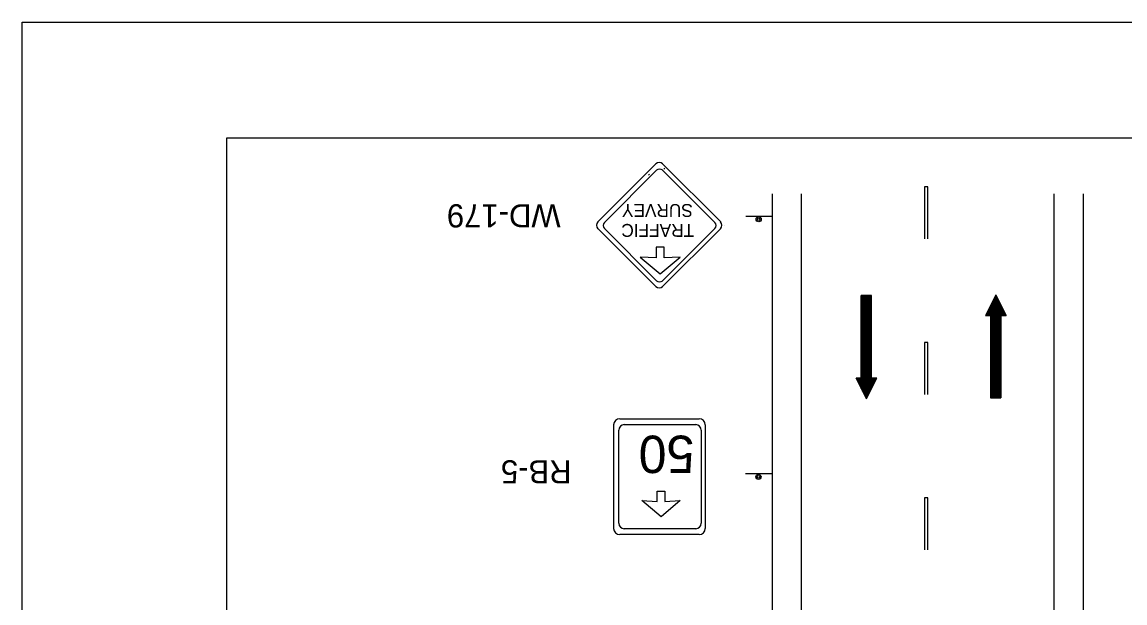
# Model space of a CAD drawing. Extents: x 1361 to 1577, y 123 to 402.
# Drawn here: x 1361.1 to 1464.1, y 347.9 to 402.1 of the extents above; entities that cross this region are included whole.
import ezdxf

# ---------------------------------------------------------------- set-up
doc = ezdxf.new("R2010")
doc.units = 0
for name, color, linetype in [('Level 10', 7, 'Continuous'), ('Level 2', 7, 'Continuous'), ('Level 44', 7, 'Continuous'), ('Level 60', 7, 'Continuous')]:
    doc.layers.add(name, color=color, linetype=linetype)

msp = doc.modelspace()

# ---------------------------------------------------------------- linework, layer by layer
at = {"layer": 'Level 10'}
for p, q in [((1431.16, 386.06), (1431.16, 139.68)), ((1433.87, 386.06), (1433.87, 139.68)), ((1457.45, 386.06), (1457.45, 139.68)), ((1460.18, 386.06), (1460.18, 139.68)), ((1439.47, 368.86), (1439.47, 376.56)), ((1440.43, 376.56), (1439.47, 376.56)), ((1439.47, 367.89), (1439.47, 376.56)), ((1439.59, 367.65), (1439.59, 376.56)), ((1439.71, 367.41), (1439.71, 376.56)), ((1439.83, 367.17), (1439.83, 376.56)), ((1439.95, 366.93), (1439.95, 376.56)), ((1440.07, 367.17), (1440.07, 376.56)), ((1440.19, 367.41), (1440.19, 376.56)), ((1440.31, 367.65), (1440.31, 376.56)), ((1440.43, 368.86), (1440.43, 376.56)), ((1440.43, 367.89), (1440.43, 376.56)), ((1452.02, 376.63), (1451.06, 374.71)), ((1451.66, 375.91), (1451.66, 367.01)), ((1451.78, 376.15), (1451.78, 367.01)), ((1451.9, 376.39), (1451.9, 367.01)), ((1452.02, 376.63), (1452.02, 367.01)), ((1452.02, 376.63), (1452.98, 374.71)), ((1452.14, 376.39), (1452.14, 367.01)), ((1452.26, 376.15), (1452.26, 367.01)), ((1452.38, 375.91), (1452.38, 367.01)), ((1451.18, 374.95), (1451.18, 374.71)), ((1451.3, 375.19), (1451.3, 374.71)), ((1451.42, 375.43), (1451.42, 374.71)), ((1451.54, 375.67), (1451.54, 367.01)), ((1452.5, 375.67), (1452.5, 367.01)), ((1452.62, 375.43), (1452.62, 374.71)), ((1452.74, 375.19), (1452.74, 374.71)), ((1452.86, 374.95), (1452.86, 374.71)), ((1451.06, 374.71), (1451.54, 374.71)), ((1451.54, 374.71), (1451.54, 367.01)), ((1452.5, 374.71), (1452.5, 367.01)), ((1452.5, 374.71), (1452.98, 374.71)), ((1439.95, 366.93), (1438.99, 368.86)), ((1439.47, 368.86), (1438.99, 368.86)), ((1439.11, 368.62), (1439.11, 368.86)), ((1439.23, 368.38), (1439.23, 368.86)), ((1439.35, 368.13), (1439.35, 368.86)), ((1439.95, 366.93), (1440.91, 368.86)), ((1440.91, 368.86), (1440.43, 368.86)), ((1440.55, 368.13), (1440.55, 368.86)), ((1440.67, 368.38), (1440.67, 368.86)), ((1440.79, 368.62), (1440.79, 368.86)), ((1451.54, 367.01), (1452.5, 367.01))]:
    msp.add_line(p, q, dxfattribs=at)
at = {"layer": 'Level 2'}
for p, q in [((1421.04, 388.37), (1421.14, 388.47)), ((1419.6, 387.81), (1419.7, 387.91)), ((1445.38, 386.7), (1445.38, 381.86)), ((1445.67, 386.7), (1445.38, 386.7)), ((1445.67, 381.86), (1445.67, 386.7)), ((1445.38, 372.18), (1445.38, 367.34)), ((1445.67, 372.18), (1445.38, 372.18)), ((1445.67, 367.34), (1445.67, 372.18)), ((1445.38, 357.67), (1445.38, 352.83)), ((1445.67, 357.67), (1445.38, 357.67)), ((1445.67, 352.83), (1445.67, 357.67))]:
    msp.add_line(p, q, dxfattribs=at)
at = {"layer": 'Level 44'}
for p, q in [((1420.28, 388.87), (1414.88, 383.45)), ((1415.48, 383.39), (1420.35, 388.26)), ((1426.34, 383.45), (1420.92, 388.87)), ((1420.92, 388.26), (1425.8, 383.39)), ((1426.33, 383.45), (1426.34, 383.45)), ((1426.66, 383.13), (1426.66, 383.13)), ((1431.09, 383.96), (1428.69, 383.96)), ((1414.88, 382.81), (1420.28, 377.41)), ((1420.35, 377.95), (1415.48, 382.82)), ((1425.8, 382.82), (1420.92, 377.95)), ((1420.92, 377.41), (1426.34, 382.81)), ((1420.31, 381.07), (1420.31, 380.08)), ((1421.06, 381.07), (1420.32, 381.07)), ((1421.06, 380.08), (1421.06, 381.07)), ((1420.31, 380.08), (1418.83, 380.16)), ((1418.83, 380.16), (1420.68, 378.59)), ((1420.68, 378.59), (1422.55, 380.16)), ((1422.55, 380.16), (1421.06, 380.08)), ((1416.92, 365.06), (1424.33, 365.06)), ((1417.34, 364.52), (1424.01, 364.52)), ((1416.35, 354.83), (1416.35, 364.49)), ((1416.82, 355.31), (1416.82, 364)), ((1424.52, 364), (1424.52, 355.31)), ((1424.52, 364), (1424.52, 364)), ((1424.9, 364.49), (1424.9, 354.83)), ((1424.9, 364.49), (1424.9, 364.49)), ((1431.08, 359.91), (1428.67, 359.91)), ((1424.33, 354.26), (1416.92, 354.26)), ((1424.01, 354.79), (1417.34, 354.79))]:
    msp.add_line(p, q, dxfattribs=at)
msp.add_lwpolyline([(1422.56, 357.42), (1420.77, 355.91), (1418.99, 357.42), (1420.42, 357.34), (1420.42, 358.3), (1421.13, 358.3), (1421.13, 357.34)], close=True, dxfattribs=at)
for centre, radius in [((1429.89, 383.69), 0.241), ((1429.89, 383.69), 0.12), ((1429.87, 359.64), 0.241), ((1429.87, 359.64), 0.12)]:
    msp.add_circle(centre, radius, dxfattribs=at)
for centre, radius, start, end in [((1420.6, 388.54), 0.453, 45, 135), ((1420.64, 387.97), 0.407, 45, 135), ((1415.2, 383.13), 0.453, 135, 225), ((1415.77, 383.11), 0.407, 135, 225), ((1425.5, 383.11), 0.407, 315, 45), ((1426.01, 383.13), 0.453, 315, 45), ((1420.64, 378.24), 0.407, 225, 315), ((1420.6, 377.73), 0.453, 225, 315), ((1416.92, 364.49), 0.572, 90, 180), ((1417.34, 364), 0.514, 90, 180), ((1424.01, 364), 0.514, 360, 90), ((1424.33, 364.49), 0.572, 360, 90), ((1417.34, 355.31), 0.514, 180, 270), ((1424.01, 355.31), 0.514, 270, 360), ((1416.92, 354.83), 0.572, 180, 270), ((1424.33, 354.83), 0.572, 270, 360)]:
    msp.add_arc(centre, radius, start, end, dxfattribs=at)
at = {"layer": 'Level 60'}
msp.add_line((1361.11, 402.1), (1361.11, 402.1), dxfattribs=at)
for points in [[(1361.11, 402.1), (1577.11, 402.1), (1577.11, 123.1), (1361.11, 123.1)], [(1380.24, 391.29), (1567.11, 391.29), (1567.11, 133.91), (1380.24, 133.91)]]:
    msp.add_lwpolyline(points, close=True, dxfattribs=at)

# ---------------------------------------------------------------- texts
at = {"layer": 'Level 10'}
for s, p in [('WD-179', (1411.4, 385.09)), ('RB-5', (1412.42, 361.19))]:
    msp.add_text(s, height=2.165, rotation=180, dxfattribs=at).set_placement(p)
at = {"layer": 'Level 44'}
for s, height, p in [('SURVEY', 1.203, (1423.74, 385.11)), ('TRAFFIC', 1.203, (1423.86, 383.25)), ('50', 3.494, (1423.88, 363.49))]:
    msp.add_text(s, height=height, rotation=180, dxfattribs=at).set_placement(p)

doc.saveas('drawing.dxf')
